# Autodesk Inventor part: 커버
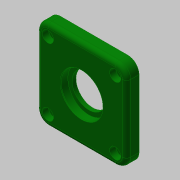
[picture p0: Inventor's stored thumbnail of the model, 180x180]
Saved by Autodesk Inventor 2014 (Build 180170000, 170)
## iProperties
Created: 2019-09
Part Number: 커버
Material: 알루미늄 6061
Document SubType Name: Modeling
Designer: mduedu
Density: 2.71 g/cm^3
Appearance: 진녹색
Mass: 80.7314 g
Surface Area: 109.271 cm^2
Volume: 29.7902 cm^3
Author: mduedu
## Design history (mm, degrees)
sketch "스케치1"
  geometry: L1 (-32, -32)-(32, -32); L2 (32, -32)-(32, 32); L3 (32, 32)-(-32, 32); L4 (-32, 32)-(-32, -32); L5 (-32, -32)-(32, 32); L6 (32, -32)-(-32, 32); 1 further point
  constraints: 12 end point, 2 midpoint, 2 parallel, 1 horizontal, 1 perpendicular
  dimensions: "d44" = 64 distance of L3.end L2.end; "d45" = 64 distance of L2.end L1.end
extrude "돌출1" new body sketch "스케치1" distance "d1" = 9; taper "d2" = 0 deg
sketch "스케치2"
  geometry: C1 r 21 at (0, 0); 1 further point
  constraints: 1 centre point, 1 coincident
  dimensions: "d3" = 42 diameter of C1
extrude "돌출2" join sketch "스케치2" distance "d4" = 3; taper "d5" = 0 deg
hole "구멍1" diameter "d8" = 24; stored, may be unused: countersink angle "d12" = 90 deg, drill point angle "d14" = 118 deg; dims "d9" = 6, "d10" = 30, "d11" = 5.2, "d13" = 8, "d46" = 10, "d47" = 10
hole "구멍2" diameter "d17" = 37; stored, may be unused: countersink angle "d21" = 90 deg, drill point angle "d23" = 0 deg; dims "d15" = 10, "d16" = 10, "d18" = 6, "d19" = 30, "d20" = 5.2, "d22" = 4
fillet "모깎기1" dims "d24" = 3
fillet "모깎기4" dims "d48" = 8
fillet "모깎기2" dims "d25" = 3
chamfer "모따기1" distance "d27" = 0.5; stored, may be unused: second distance "d28" = 2, angle "d29" = 30 deg
chamfer "모따기2" distance "d30" = 1; stored, may be unused: second distance "d31" = 2, angle "d32" = 30 deg
sketch "스케치4"
  geometry: A1 r 8 centre (-24, 24) between (-24, 32) and (-32, 24) reference; A2 r 8 centre (24, 24) between (32, 24) and (24, 32) reference; A3 r 8 centre (24, -24) between (24, -32) and (32, -24) reference; A4 r 8 centre (-24, -24) between (-32, -24) and (-24, -32) reference; 5 further points
  constraints: 4 coincident
hole "구멍4" sketch "스케치4" at (-24, 24), (24, 24), (24, -24), (-24, -24) diameter "d49" = 4.5; stored, may be unused: countersink angle "d53" = 90 deg, drill point angle "d55" = 118 deg; dims "d50" = 6, "d51" = 8, "d52" = 4.4, "d54" = 8
node "솔리드1"
